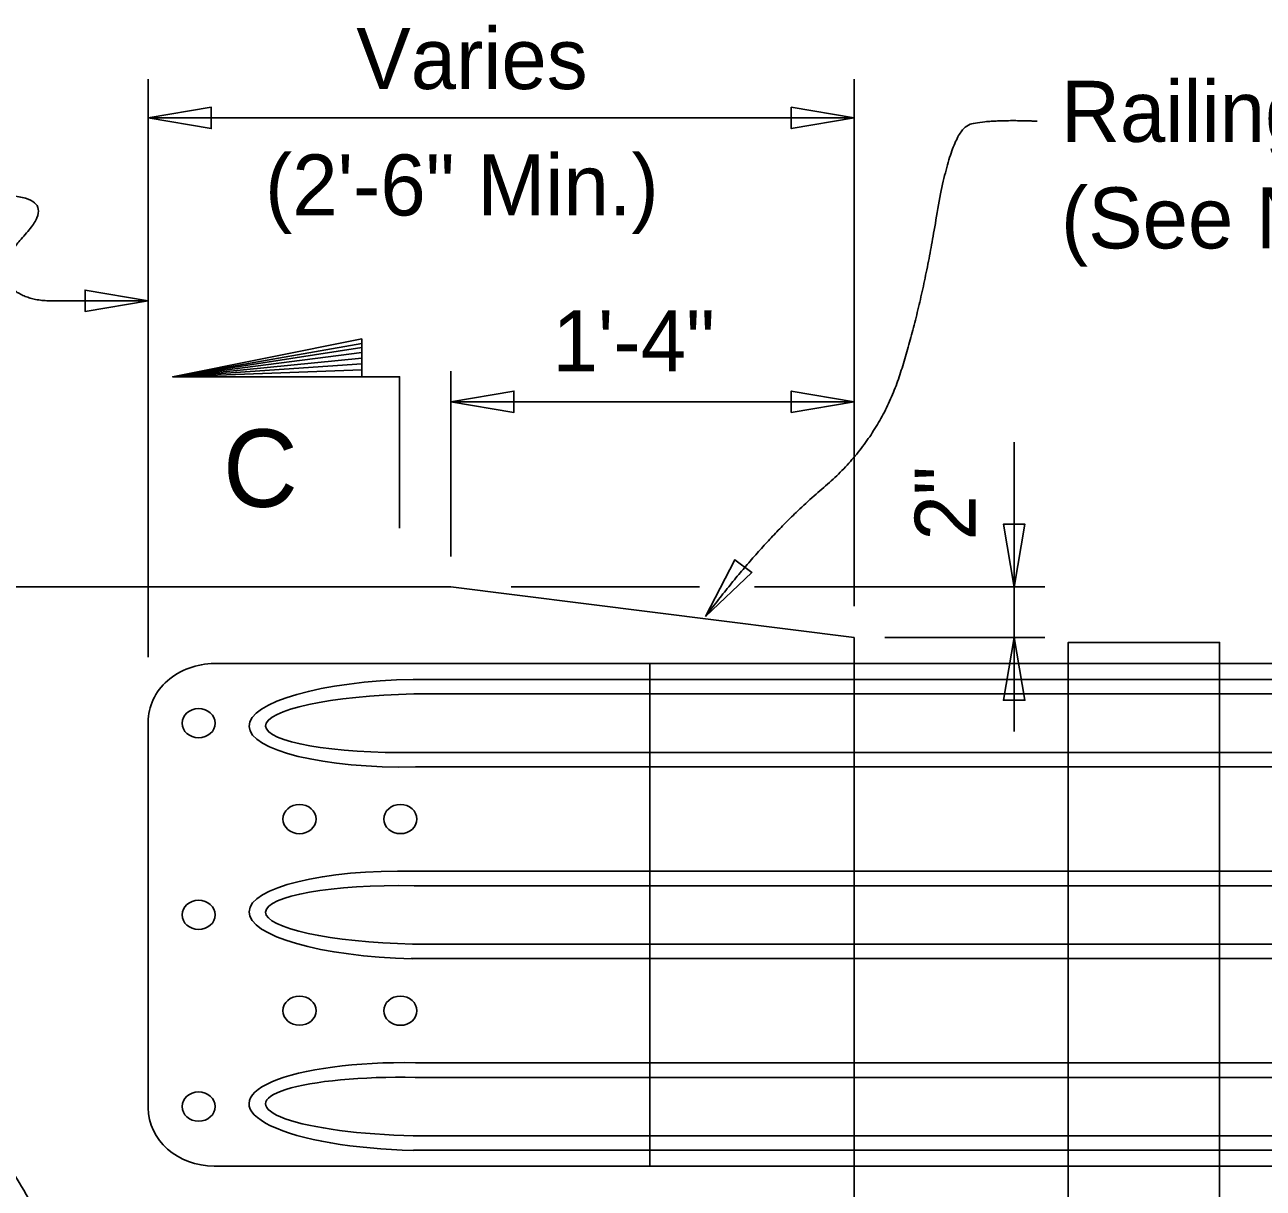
# Model space of a CAD drawing. Extents: x 1.5 to 68.7, y 0 to 31.
# Drawn here: x 28.879 to 32.972, y 12.779 to 16.622 of the extents above; entities that cross this region are included whole.
import ezdxf

# ---------------------------------------------------------------- set-up
doc = ezdxf.new("R2010")
doc.units = 0
for name, color, linetype in [('AdhocPoint_dp', 7, 'Continuous'), ('Patterning', 7, 'Continuous'), ('PlotBorder_dp', 7, 'Continuous'), ('TextMisc', 7, 'Continuous')]:
    doc.layers.add(name, color=color, linetype=linetype)

# ---------------------------------------------------------------- blocks, each defined once
blk = doc.blocks.new('Terminator-Arrow')
at = {"layer": 'AdhocPoint_dp'}
blk.add_lwpolyline([(0, 0), (-0.0004099, 0.0000694), (-0.0004099, -0.0000694)], close=True, dxfattribs=at)

msp = doc.modelspace()

# ---------------------------------------------------------------- linework, layer by layer
at = {"layer": 'AdhocPoint_dp'}
for p, q in [((29.2871, 14.5331), (29.2871, 16.4428)), ((31.6205, 14.7016), (31.6205, 16.4428)), ((31.6205, 16.3147), (29.2871, 16.3147)), ((29.3681, 15.4594), (29.9931, 15.5694)), ((29.9931, 15.5561), (29.3681, 15.4594)), ((29.3681, 15.4594), (29.9931, 15.5394)), ((29.9931, 15.5211), (29.3681, 15.4594)), ((29.3681, 15.4594), (29.9931, 15.5027)), ((29.9931, 15.4827), (29.3681, 15.4594)), ((30.2872, 14.8661), (30.2872, 15.4777)), ((30.2872, 15.3768), (31.6205, 15.3768)), ((32.1489, 15.2437), (32.1489, 14.2876)), ((30.4865, 14.7653), (31.1092, 14.7653)), ((31.2909, 14.7653), (32.2497, 14.7653)), ((31.7213, 14.5986), (32.2497, 14.5986))]:
    msp.add_line(p, q, dxfattribs=at)
for points in [[(29.2871, 16.3147), (29.4954, 16.2794), (29.4954, 16.3499)], [(31.6205, 16.3147), (31.4123, 16.3499), (31.4123, 16.2794)], [(29.2871, 15.7107), (29.0789, 15.7459), (29.0789, 15.6754)], [(30.2872, 15.3769), (30.4955, 15.3416), (30.4955, 15.4121)], [(31.6205, 15.3769), (31.4123, 15.4121), (31.4123, 15.3416)], [(31.1287, 14.6675), (31.2824, 14.8124), (31.2261, 14.855)]]:
    msp.add_lwpolyline(points, close=True, dxfattribs=at)
msp.add_lwpolyline([(30.1181, 14.9594), (30.1181, 15.4594), (29.3681, 15.4594), (29.9931, 15.5844), (29.9931, 15.4594)], dxfattribs=at)
for points in [[(32.2251, 16.3037), (32.0694, 16.3102), (31.9396, 16.2777), (31.8423, 15.6869), (31.6996, 15.2453), (31.3298, 14.9337), (31.1287, 14.6675)], [(28.3524, 16.0586), (28.5909, 16.0586), (28.997, 16.0586), (28.7722, 15.8101), (28.879, 15.7106), (29.0455, 15.7106), (29.2872, 15.7106)], [(28.4708, 12.9203), (28.7034, 12.864), (28.7449, 13.0099), (29.089, 12.3912), (29.2714, 12.2154)]]:
    msp.add_open_spline(points, degree=2, dxfattribs=at)
at = {"layer": 'Patterning'}
for p, q in [((29.5056, 14.512), (36.5106, 14.512)), ((30.9451, 12.852), (30.9451, 14.5121)), ((30.1632, 14.4598), (36.5106, 14.4598)), ((30.1645, 14.4116), (36.5106, 14.4116)), ((29.2871, 13.0448), (29.2871, 14.3193)), ((30.1692, 14.2188), (36.5106, 14.2188)), ((30.1703, 14.1705), (36.5106, 14.1705)), ((30.1669, 13.8266), (36.5106, 13.8266)), ((30.1656, 13.7783), (36.5106, 13.7783)), ((30.1604, 13.5855), (36.5106, 13.5855)), ((30.1563, 13.5374), (36.5106, 13.5374)), ((30.1703, 13.1934), (36.5106, 13.1934)), ((30.1692, 13.1452), (36.5106, 13.1452)), ((30.1629, 12.9524), (36.5106, 12.9524)), ((30.164, 12.9042), (36.5106, 12.9042)), ((29.5056, 12.8519), (36.5106, 12.8519))]:
    msp.add_line(p, q, dxfattribs=at)
msp.add_lwpolyline([(32.8274, 10.853), (32.8274, 14.5819), (32.3274, 14.5819), (32.3274, 10.853)], dxfattribs=at)
for centre, major_axis, ratio, start_param, end_param in [((29.5058, 14.3192), (0.2185, 0), 0.882613, 1.570796, 3.141593), ((30.1669, 14.3152), (-0.5464, -0.0102), 0.264749, 4.713933, 7.855525), ((30.1669, 14.3152), (-0.4917, -0.0093), 0.196063, 4.713495, 7.855087), ((30.1633, 13.6819), (-0.5428, 0.0103), 0.266477, 4.71081, 7.852402), ((30.1633, 13.6819), (-0.4882, 0.0094), 0.197486, 4.711258, 7.85285), ((30.1669, 13.0488), (-0.5464, 0.0102), 0.264749, 4.710845, 7.852438), ((30.1669, 13.0488), (-0.4917, 0.0093), 0.196063, 4.711283, 7.852876), ((29.5058, 13.0447), (0.2185, 0), 0.882613, 3.141593, 4.712389)]:
    msp.add_ellipse(centre, major_axis=major_axis, ratio=ratio, start_param=start_param, end_param=end_param, dxfattribs=at)
for centre in [(29.4539, 14.3152), (29.7872, 13.9985), (30.1206, 13.9986), (29.4539, 13.682), (29.7872, 13.3655), (30.1206, 13.3654), (29.4539, 13.0488)]:
    msp.add_ellipse(centre, major_axis=(0.0547, 0), ratio=0.882613, dxfattribs=at)
at = {"layer": 'PlotBorder_dp'}
for p, q in [((30.2872, 14.7653), (25.4726, 14.7653)), ((30.2872, 14.7653), (31.6205, 14.5986)), ((31.6205, 14.5986), (31.6205, 11.932))]:
    msp.add_line(p, q, dxfattribs=at)

# ---------------------------------------------------------------- block references
at = {"layer": 'AdhocPoint_dp', "xscale": 506.349, "yscale": 512.1577380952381}
for p, rotation in [((32.1485, 14.765), -90), ((32.1485, 14.5983), 90)]:
    msp.add_blockref('Terminator-Arrow', p, dxfattribs=dict(at, rotation=rotation))

# ---------------------------------------------------------------- texts
at = {"layer": 'AdhocPoint_dp'}
for s, p in [('Railing End Transition ', (32.3035, 16.2355)), ('(See Note 2)', (32.3035, 15.8835))]:
    msp.add_text(s, height=0.2016, dxfattribs=at).set_placement(p)
at = {"layer": 'TextMisc'}
for s, height, p in [('Varies', 0.2016, (29.975, 16.4099)), ('(2\'-6" Min.)', 0.2016, (29.6735, 15.9923)), ('1\'-4"', 0.2016, (30.6234, 15.4773)), ('C', 0.256, (29.5343, 15.0297))]:
    msp.add_text(s, height=height, dxfattribs=at).set_placement(p)
msp.add_text('2"', height=0.2016, rotation=90, dxfattribs=at).set_placement((32.0217, 14.9185))

doc.saveas('drawing.dxf')
